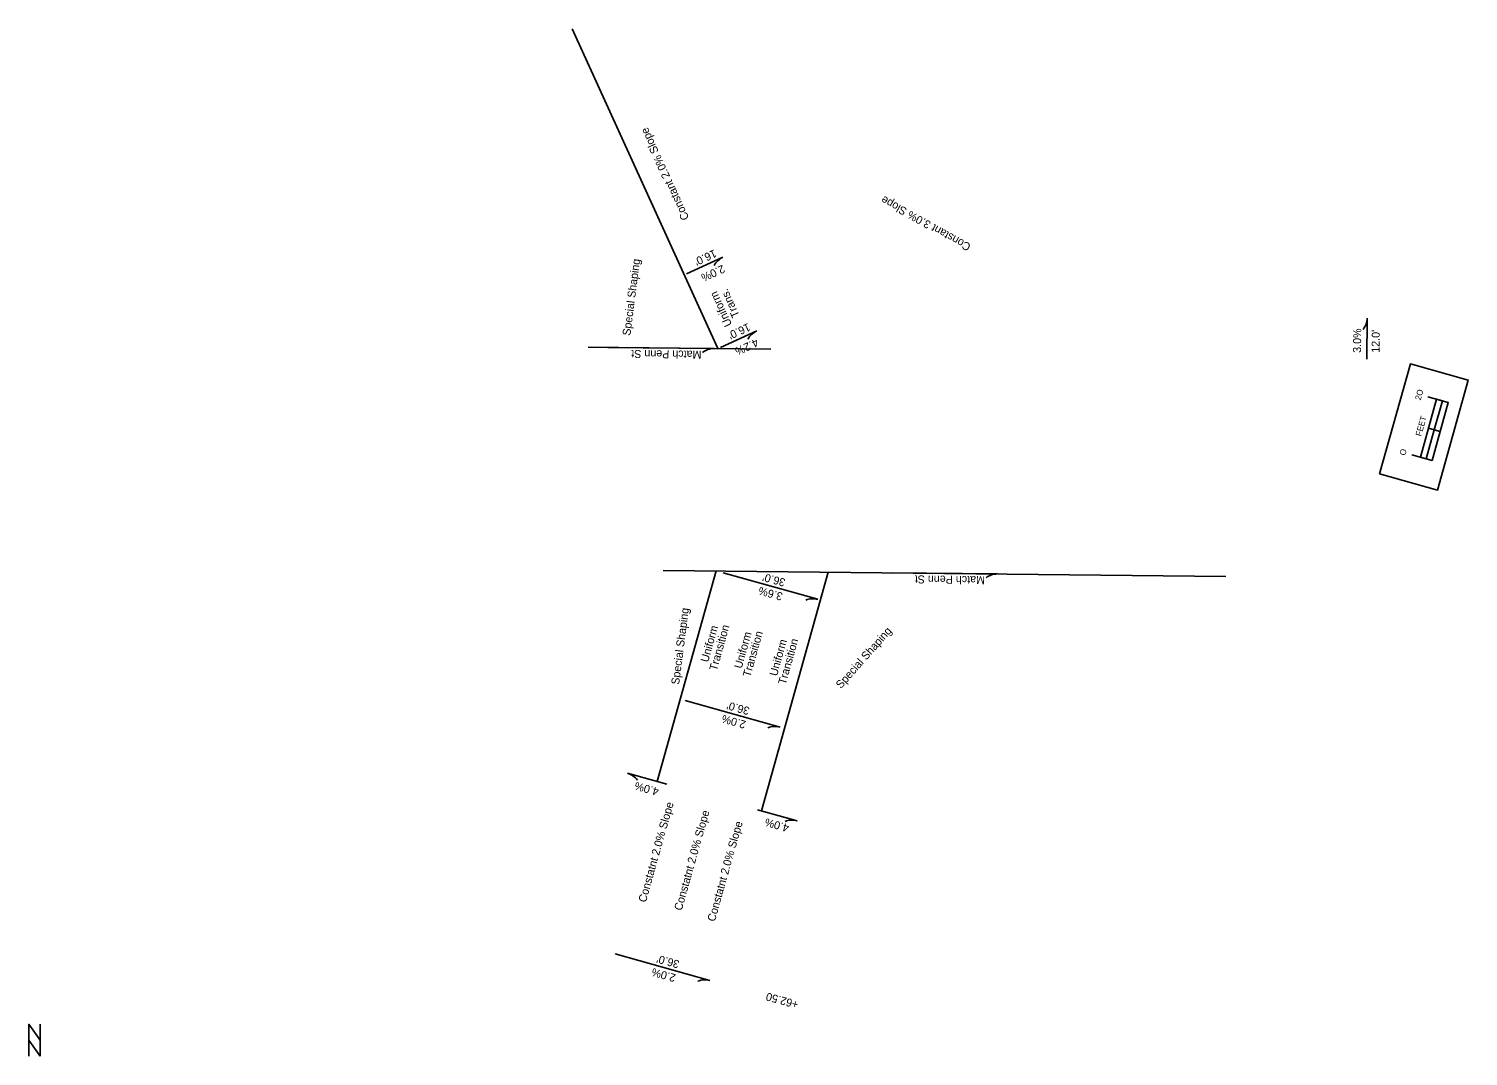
# Model space of a CAD drawing. Extents: x 20506035 to 20507470, y 7969245 to 7972296.
# Drawn here: x 20506911.7 to 20507390.9, y 7970363 to 7970705 of the extents above; entities that cross this region are included whole.
import ezdxf

# ---------------------------------------------------------------- set-up
doc = ezdxf.new("R2010")
doc.units = 0
for name, color, linetype in [('_CIVIL_CONSTRUCTION', 7, 'Continuous'), ('dsnStdLineWork', 7, 'Continuous'), ('EdgeShoulder', 7, 'Continuous')]:
    doc.layers.add(name, color=color, linetype=linetype)

msp = doc.modelspace()

# ---------------------------------------------------------------- linework, layer by layer
at = {"layer": '_CIVIL_CONSTRUCTION'}
for p, q in [((20507130.73, 7970623.47), (20507142.84, 7970628.98)), ((20507357.29, 7970608.74), (20507357.15, 7970595.09)), ((20507141.97, 7970598.95), (20507154.08, 7970604.47)), ((20507104.51, 7970598.97), (20507139.87, 7970598.58)), ((20507381.59, 7970571), (20507377.73, 7970572.07)), ((20507381.59, 7970571), (20507377.73, 7970572.07)), ((20507142.88, 7970523.93), (20507174.41, 7970515.12)), ((20507198.88, 7970523.95), (20507234.24, 7970523.56)), ((20507130.3, 7970481.4), (20507161.83, 7970472.59)), ((20507111.04, 7970457.22), (20507124.19, 7970453.55)), ((20507154.38, 7970445.11), (20507167.53, 7970441.43)), ((20507106.95, 7970397.07), (20507138.48, 7970388.26))]:
    msp.add_line(p, q, dxfattribs=at)
for points in [[(20507361.45, 7970556.9), (20507371.68, 7970593.49), (20507390.94, 7970588.11), (20507380.71, 7970551.51)], [(20507361.45, 7970556.9), (20507371.68, 7970593.49), (20507390.94, 7970588.11), (20507380.71, 7970551.51)], [(20507379.65, 7970571.54), (20507382.34, 7970581.17), (20507380.43, 7970581.7), (20507377.73, 7970572.07)], [(20507378.89, 7970561.37), (20507381.59, 7970571), (20507379.65, 7970571.54), (20507376.95, 7970561.91)]]:
    msp.add_lwpolyline(points, close=True, dxfattribs=at)
for points in [[(20507372.15, 7970563.25), (20507378.89, 7970561.37), (20507384.28, 7970580.63), (20507377.54, 7970582.51)], [(20507375.04, 7970562.44), (20507380.43, 7970581.7)]]:
    msp.add_lwpolyline(points, dxfattribs=at)
for centre, start, end in [((20507145.39, 7970623.37), 114.4617, 152.6647), ((20507351.13, 7970608.81), 321.205, 359.3556), ((20507156.63, 7970598.85), 114.4617, 152.6647), ((20507139.8, 7970592.42), 89.3742, 127.5772), ((20507234.18, 7970517.4), 89.3742, 127.5772), ((20507172.75, 7970509.18), 74.3555, 112.5586), ((20507160.16, 7970466.65), 74.3555, 112.5586), ((20507109.38, 7970451.29), 36.205, 74.3556), ((20507165.87, 7970435.5), 74.4079, 112.5586), ((20507136.81, 7970382.32), 74.3555, 112.5586)]:
    msp.add_arc(centre, 6.16, start, end, dxfattribs=at)
at = {"layer": 'dsnStdLineWork'}
for p, q in [((20507141.14, 7970598.57), (20507092.66, 7970705.02)), ((20507158.81, 7970598.38), (20507098.01, 7970599.04)), ((20507120.98, 7970454.44), (20507140.59, 7970524.57)), ((20507122.89, 7970524.76), (20507310.23, 7970522.74)), ((20507155.66, 7970444.75), (20507177.86, 7970524.17))]:
    msp.add_line(p, q, dxfattribs=at)
at = {"layer": 'EdgeShoulder'}
msp.add_lwpolyline([(20506915.55, 7970363.05), (20506911.75, 7970368.37), (20506911.75, 7970373.7), (20506915.55, 7970368.37)], close=True, dxfattribs=at)
msp.add_lwpolyline([(20506911.75, 7970363.05), (20506911.75, 7970373.7), (20506915.55, 7970368.37), (20506915.55, 7970373.7)], dxfattribs=at)

# ---------------------------------------------------------------- texts
at = {"layer": '_CIVIL_CONSTRUCTION'}
for s, height, rotation, p in [('Constant 2.0% Slope', 2.664, 114.5604, (20507131.64, 7970642.01)), ('Constant 3.0% Slope', 2.664, 150.7831, (20507225.61, 7970633.19)), ('Special Shaping', 2.664, 82.6678, (20507111.99, 7970602.77)), ("16.0'", 2.664, 204.5906, (20507139.95, 7970631.66)), ('2.0%', 2.664, 204.5906, (20507142.7, 7970626.54)), ('Uniform', 2.664, 114.4338, (20507145.92, 7970606.55)), ('Trans.', 2.664, 114.4338, (20507148.44, 7970609.57)), ("16.0'", 2.664, 204.5906, (20507151.2, 7970607.14)), ('3.0%', 2.664, 89.4845, (20507355.25, 7970597.16)), ("12.0'", 2.664, 89.4845, (20507361.43, 7970597.18)), ('4.2%', 2.664, 204.5906, (20507153.94, 7970602.02)), ('Match Penn St', 2.664, 179.2715, (20507135.7, 7970597.84)), ('2O', 2, 74.3818, (20507375.1, 7970581.25)), ('FEET', 2, 74.3818, (20507375.28, 7970569.24)), ('O', 2, 74.3818, (20507369.96, 7970562.84)), ("36.0'", 2.664, 164.4845, (20507163.84, 7970521.85)), ('Match Penn St', 2.664, 179.2715, (20507230.07, 7970522.81)), ('3.6%', 2.664, 164.4845, (20507162.93, 7970517.2)), ('Special Shaping', 2.664, 82.6678, (20507128.23, 7970486.59)), ('Uniform', 2.664, 74.3157, (20507137.89, 7970493.98)), ('Transition', 2.664, 74.3157, (20507140.79, 7970491.17)), ('Uniform', 2.664, 74.3157, (20507149.05, 7970491.89)), ('Transition', 2.664, 74.3157, (20507151.94, 7970489.08)), ('Special Shaping', 2.664, 48.3805, (20507182.13, 7970485.22)), ('Uniform', 2.664, 74.3157, (20507160.82, 7970489.38)), ('Transition', 2.664, 74.3157, (20507163.72, 7970486.57)), ("36.0'", 2.664, 164.2791, (20507151.91, 7970479.11)), ('2.0%', 2.664, 164.2791, (20507150.7, 7970474.56)), ('4.0%', 2.664, 164.4845, (20507121.7, 7970452.25)), ('Constatnt 2.0% Slope', 2.664, 74.3157, (20507117.16, 7970414.06)), ('Constatnt 2.0% Slope', 2.664, 74.3157, (20507129.09, 7970411.33)), ('Constatnt 2.0% Slope', 2.664, 74.3157, (20507140.14, 7970407.67)), ('4.0%', 2.664, 164.4845, (20507165.04, 7970440.14)), ("36.0'", 2.664, 164.2791, (20507128.55, 7970394.79)), ('2.0%', 2.664, 164.2791, (20507127.35, 7970390.23)), ('+62.50', 2.664, 164.3818, (20507168.19, 7970381.34))]:
    msp.add_text(s, height=height, rotation=rotation, dxfattribs=at).set_placement(p)

doc.saveas('drawing.dxf')
